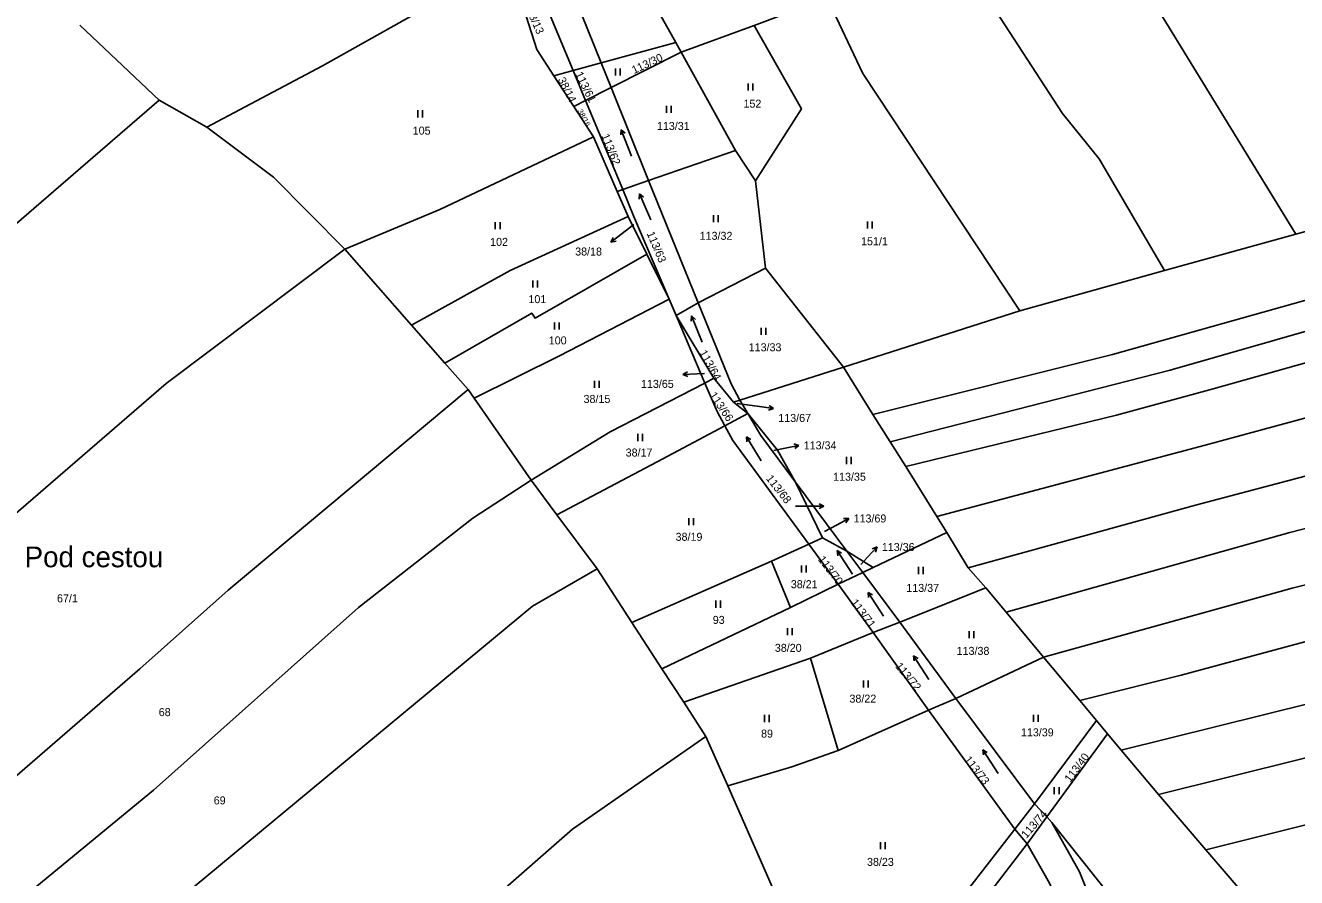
# Model space of a CAD drawing. Extents: x -7476540 to -746055, y -11317203 to -1129777.
# Drawn here: x -747546.5 to -747276.5, y -1131322.6 to -1131141.4 of the extents above; entities that cross this region are included whole.
import ezdxf

# ---------------------------------------------------------------- set-up
doc = ezdxf.new("R2010")
doc.units = 0
for name, color, linetype in [('Hranice parcel', 7, 'Continuous'), ('Parcelní čísla', 7, 'Continuous'), ('Pop  PČ popisy', 7, 'Continuous'), ('Značky kultur', 7, 'Continuous')]:
    doc.layers.add(name, color=color, linetype=linetype)

msp = doc.modelspace()

# ---------------------------------------------------------------- linework, layer by layer
at = {"layer": 'Hranice parcel'}
for p, q in [((-747408.38, -1131145.07), (-747431.95, -1131103.02)), ((-747440.84, -1131108.03), (-747424.22, -1131149.41)), ((-747430.18, -1131151.04), (-747446.81, -1131111.05)), ((-747376.22, -1131135.6), (-747391.74, -1131141.48)), ((-747518.15, -1131157.34), (-747534.94, -1131141.41)), ((-747407.22, -1131147.14), (-747391.74, -1131141.48)), ((-747424.22, -1131149.41), (-747408.38, -1131145.07)), ((-747407.22, -1131147.14), (-747408.38, -1131145.07)), ((-747422.11, -1131154.66), (-747407.22, -1131147.14)), ((-747395.7, -1131168), (-747407.22, -1131147.14)), ((-747430.18, -1131151.04), (-747424.22, -1131149.41)), ((-747424.22, -1131149.41), (-747422.11, -1131154.66)), ((-747434.26, -1131152.16), (-747430.18, -1131151.04)), ((-747434.26, -1131152.16), (-747430.03, -1131158.67)), ((-747427.53, -1131157.41), (-747430.18, -1131151.04)), ((-747427.53, -1131157.41), (-747422.11, -1131154.66)), ((-747422.11, -1131154.66), (-747414.16, -1131174.44)), ((-747508, -1131163.09), (-747518.15, -1131157.34)), ((-747430.03, -1131158.67), (-747427.53, -1131157.41)), ((-747430.03, -1131158.67), (-747425.84, -1131165.11)), ((-747419.66, -1131176.34), (-747427.53, -1131157.41)), ((-747425.84, -1131165.11), (-747420.83, -1131176.75)), ((-747414.16, -1131174.44), (-747395.7, -1131168)), ((-747391.42, -1131174.47), (-747395.7, -1131168)), ((-747419.66, -1131176.34), (-747414.16, -1131174.44)), ((-747414.16, -1131174.44), (-747403.63, -1131200.37)), ((-747389.33, -1131193.02), (-747391.42, -1131174.47)), ((-747420.83, -1131176.75), (-747419.66, -1131176.34)), ((-747420.83, -1131176.75), (-747418.53, -1131182.09)), ((-747418.53, -1131182.09), (-747414.55, -1131190.08)), ((-747304.55, -1131193.5), (-747276.68, -1131185.78)), ((-747464.5, -1131205.17), (-747478.68, -1131189)), ((-747414.55, -1131190.08), (-747409.79, -1131199.63)), ((-747403.63, -1131200.37), (-747389.33, -1131193.02)), ((-747372.79, -1131214.07), (-747389.33, -1131193.02)), ((-747335.3, -1131202.07), (-747304.55, -1131193.5)), ((-747408.32, -1131203.08), (-747409.79, -1131199.63)), ((-747408.32, -1131203.08), (-747403.63, -1131200.37)), ((-747372.79, -1131214.07), (-747335.3, -1131202.07)), ((-747402.18, -1131217.46), (-747408.32, -1131203.08)), ((-747408.32, -1131203.08), (-747400.3, -1131216.43)), ((-747457.41, -1131213.25), (-747464.5, -1131205.17)), ((-747452.5, -1131218.84), (-747457.41, -1131213.25)), ((-747394.81, -1131221.1), (-747372.79, -1131214.07)), ((-747366.49, -1131224.14), (-747372.79, -1131214.07)), ((-747402.18, -1131217.46), (-747400.3, -1131216.43)), ((-747400.3, -1131216.43), (-747396.13, -1131221.54)), ((-747451.24, -1131220.66), (-747452.5, -1131218.84)), ((-747451.24, -1131220.66), (-747439.12, -1131238.12)), ((-747396.13, -1131221.54), (-747394.81, -1131221.1)), ((-747393.08, -1131223.94), (-747396.13, -1131221.54)), ((-747394.81, -1131221.1), (-747393.08, -1131223.94)), ((-747397.95, -1131226.54), (-747393.08, -1131223.94)), ((-747362.83, -1131229.98), (-747366.49, -1131224.14)), ((-747359.55, -1131235.22), (-747362.83, -1131229.98)), ((-747352.93, -1131245.79), (-747359.55, -1131235.22)), ((-747439.12, -1131238.12), (-747433.68, -1131245.43)), ((-747377.23, -1131250.36), (-747382.92, -1131238.52)), ((-747382.92, -1131238.52), (-747372.02, -1131253.19)), ((-747433.68, -1131245.43), (-747425.11, -1131256.95)), ((-747350.79, -1131249.21), (-747352.93, -1131245.79)), ((-747380.11, -1131251.72), (-747377.23, -1131250.36)), ((-747377.23, -1131250.36), (-747372.02, -1131253.19)), ((-747366.48, -1131256.66), (-747350.79, -1131249.21)), ((-747346.25, -1131256.73), (-747350.79, -1131249.21)), ((-747388.07, -1131255.34), (-747380.11, -1131251.72)), ((-747373.91, -1131260.21), (-747380.11, -1131251.72)), ((-747372.02, -1131253.19), (-747366.48, -1131256.66)), ((-747372.02, -1131253.19), (-747368.67, -1131257.7)), ((-747417.7, -1131268.35), (-747388.07, -1131255.34)), ((-747388.07, -1131255.34), (-747384.01, -1131265.18)), ((-747425.11, -1131256.95), (-747417.7, -1131268.35)), ((-747373.91, -1131260.21), (-747368.67, -1131257.7)), ((-747368.67, -1131257.7), (-747366.48, -1131256.66)), ((-747368.67, -1131257.7), (-747360.8, -1131268.29)), ((-747342.53, -1131260.96), (-747346.25, -1131256.73)), ((-747373.91, -1131260.21), (-747384.01, -1131265.18)), ((-747366.42, -1131270.45), (-747373.91, -1131260.21)), ((-747360.8, -1131268.29), (-747342.53, -1131260.96)), ((-747338.19, -1131266.17), (-747342.53, -1131260.96)), ((-747384.01, -1131265.18), (-747411.33, -1131278.16)), ((-747330.24, -1131275.71), (-747338.19, -1131266.17)), ((-747411.33, -1131278.16), (-747417.7, -1131268.35)), ((-747366.42, -1131270.45), (-747360.8, -1131268.29)), ((-747360.8, -1131268.29), (-747348.89, -1131284.46)), ((-747379.74, -1131275.95), (-747366.42, -1131270.45)), ((-747354.67, -1131286.99), (-747366.42, -1131270.45)), ((-747406.7, -1131285.28), (-747379.74, -1131275.95)), ((-747379.74, -1131275.95), (-747373.86, -1131295.58)), ((-747348.89, -1131284.46), (-747330.24, -1131275.71)), ((-747322.57, -1131284.9), (-747330.24, -1131275.71)), ((-747411.33, -1131278.16), (-747406.7, -1131285.28)), ((-747401.97, -1131292.55), (-747406.7, -1131285.28)), ((-747354.67, -1131286.99), (-747348.89, -1131284.46)), ((-747348.89, -1131284.46), (-747332.21, -1131306.86)), ((-747319.02, -1131289.16), (-747322.57, -1131284.9)), ((-747373.86, -1131295.58), (-747354.67, -1131286.99)), ((-747336.38, -1131312.26), (-747354.67, -1131286.99)), ((-747332.21, -1131306.86), (-747319.02, -1131289.16)), ((-747316.65, -1131292.01), (-747319.02, -1131289.16)), ((-747397.34, -1131303.04), (-747401.97, -1131292.55)), ((-747316.65, -1131292.01), (-747329.56, -1131309.63)), ((-747313.75, -1131295.48), (-747316.65, -1131292.01)), ((-747305.83, -1131304.88), (-747313.75, -1131295.48)), ((-747397.34, -1131303.04), (-747384.78, -1131331.55)), ((-747336.38, -1131312.26), (-747332.21, -1131306.86)), ((-747332.21, -1131306.86), (-747329.56, -1131309.63)), ((-747295.77, -1131316.67), (-747305.83, -1131304.88)), ((-747329.56, -1131309.63), (-747333.76, -1131315.41)), ((-747328.48, -1131310.88), (-747329.56, -1131309.63)), ((-747370.27, -1131355.92), (-747336.38, -1131312.26)), ((-747333.76, -1131315.41), (-747336.38, -1131312.26)), ((-747286.32, -1131327.71), (-747295.77, -1131316.67))]:
    msp.add_line(p, q, dxfattribs=at)
for points in [[(-747455.08, -1130941.09), (-747407, -1130998.24), (-747346.3, -1131076.82), (-747308.86, -1131133.19), (-747276.68, -1131185.78)], [(-747466.65, -1130957.41), (-747426.05, -1131003.14), (-747390.52, -1131051.98), (-747379.77, -1131069.99), (-747357.62, -1131107.84), (-747342.16, -1131135.57), (-747326.23, -1131160.19), (-747318.42, -1131169.83), (-747304.55, -1131193.5)], [(-747444.14, -1131128.36), (-747441.29, -1131135.89), (-747437.88, -1131146.58), (-747434.26, -1131152.16)], [(-747376.22, -1131135.6), (-747368.67, -1131151.69), (-747335.3, -1131202.07)], [(-747464.26, -1131139.24), (-747483.41, -1131150.03), (-747508, -1131163.09)], [(-747366.49, -1131224.14), (-747315.64, -1131211.37), (-747239.01, -1131189.85), (-747208.02, -1131183.24), (-747142.94, -1131169.86), (-747059.23, -1131151.85), (-746994.26, -1131139.92)], [(-747391.74, -1131141.48), (-747381.7, -1131159.18), (-747391.42, -1131174.47)], [(-747362.83, -1131229.98), (-747303.37, -1131214.71), (-747236.14, -1131195.43), (-747183.65, -1131184.91), (-747140.79, -1131175.19), (-747094.5, -1131166.43), (-747035.79, -1131154.71), (-746990.07, -1131145.5)], [(-747359.55, -1131235.22), (-747314.76, -1131224.28), (-747294.21, -1131218.7), (-747239.88, -1131203.41), (-747217.65, -1131198.22), (-747179.1, -1131189.54), (-747110.35, -1131174.95), (-747094.58, -1131172.24), (-747057.06, -1131164.91), (-746987.65, -1131152.16)], [(-747637.6, -1131258.56), (-747605.36, -1131233.4), (-747586.04, -1131216.89), (-747564.17, -1131197.09), (-747518.15, -1131157.34)], [(-747478.68, -1131189), (-747493.84, -1131173.69), (-747508, -1131163.09)], [(-747352.93, -1131245.79), (-747295.96, -1131230.66), (-747233.75, -1131213.76), (-747157.12, -1131196.99), (-747060.9, -1131176.27), (-747030, -1131171.43), (-746983.59, -1131163.34)], [(-747425.84, -1131165.11), (-747458.47, -1131180.59), (-747478.68, -1131189)], [(-747409.79, -1131199.63), (-747417.35, -1131181.9), (-747419.66, -1131176.34)], [(-747346.25, -1131256.73), (-747297.98, -1131243.4), (-747234.57, -1131226.59), (-747209.63, -1131221.41), (-747174.99, -1131213.76), (-747135.39, -1131204.28), (-747094.05, -1131195.6), (-747052.94, -1131188.25), (-746980.29, -1131175.39)], [(-747276.68, -1131185.78), (-747264.57, -1131182.48), (-747243.06, -1131175.98)], [(-747418.53, -1131182.09), (-747443.59, -1131193.55), (-747464.5, -1131205.17)], [(-747338.19, -1131266.17), (-747277.98, -1131249.2), (-747235.43, -1131238.28), (-747213.21, -1131234.14), (-747187.16, -1131228.96), (-747140.48, -1131218.28), (-747086.15, -1131207.37), (-747047.59, -1131199.64), (-746976.21, -1131185.45)], [(-747478.68, -1131189), (-747516.61, -1131217.55), (-747562.75, -1131257.36), (-747584.62, -1131275.69), (-747613.72, -1131296.16)], [(-747414.55, -1131190.08), (-747438.27, -1131203.66), (-747438.96, -1131202.58), (-747457.41, -1131213.25)], [(-747330.24, -1131275.71), (-747277.42, -1131261.08), (-747228.35, -1131248.89), (-747189.96, -1131241.4), (-747149.33, -1131232.63), (-747125.6, -1131227.7), (-747062.34, -1131215.02), (-746993.98, -1131202.44), (-746969.25, -1131197.46)], [(-747409.79, -1131199.63), (-747433.07, -1131211.69), (-747451.24, -1131220.66)], [(-747403.63, -1131200.37), (-747396.62, -1131217.65), (-747394.81, -1131221.1)], [(-747322.57, -1131284.9), (-747301.01, -1131279.52), (-747228.28, -1131259.93), (-747190.83, -1131253.47), (-747160.64, -1131247.09), (-747111.02, -1131236.65), (-747064.81, -1131227), (-747042.19, -1131222.79), (-746964.73, -1131206.9)], [(-747439.12, -1131238.12), (-747422.3, -1131227.8), (-747402.18, -1131217.46)], [(-747397.95, -1131226.54), (-747399.59, -1131223.53), (-747402.18, -1131217.46)], [(-747587.97, -1131330.74), (-747567.99, -1131317.8), (-747522.26, -1131278.21), (-747503.48, -1131261.46), (-747452.5, -1131218.84)], [(-747313.75, -1131295.48), (-747253.05, -1131280.4), (-747231.07, -1131274.58), (-747201.09, -1131268.16), (-747174.02, -1131263.18), (-747155.54, -1131259.35), (-747082.77, -1131244.23), (-747040.5, -1131235.77), (-746958.82, -1131219.23)], [(-747393.08, -1131223.94), (-747390.29, -1131228.61), (-747382.92, -1131238.52)], [(-747382.92, -1131238.52), (-747386.77, -1131231.73), (-747393.08, -1131223.94)], [(-747433.68, -1131245.43), (-747412.33, -1131234.19), (-747397.95, -1131226.54)], [(-747380.11, -1131251.72), (-747396.26, -1131229.64), (-747397.95, -1131226.54)], [(-747305.83, -1131304.88), (-747229.31, -1131285.82), (-747172.59, -1131275.8), (-747161.6, -1131273.01), (-747136.9, -1131266.58), (-747124.63, -1131263.55), (-747104.54, -1131259.94), (-747060.99, -1131251.11), (-747007.85, -1131241), (-746953.9, -1131229.5)], [(-747573.75, -1131348.78), (-747519.29, -1131304), (-747475.75, -1131265.13), (-747451.48, -1131246.17), (-747439.12, -1131238.12)], [(-747295.77, -1131316.67), (-747260.4, -1131307.82), (-747220.48, -1131297.78), (-747153.89, -1131284.38), (-747109.03, -1131274.27), (-747084.89, -1131269.09), (-747048.4, -1131261.6), (-746996.46, -1131251.25), (-746948.48, -1131240.82)], [(-747560.74, -1131366.12), (-747532.83, -1131342.86), (-747438.82, -1131264.87), (-747425.11, -1131256.95)], [(-747534.26, -1131400.17), (-747480.38, -1131356.14), (-747430.3, -1131312.29), (-747401.97, -1131292.55)], [(-747373.86, -1131295.58), (-747383.75, -1131299), (-747397.34, -1131303.04)], [(-747281.5, -1131480.62), (-747293.52, -1131448.9), (-747294.79, -1131442.89), (-747294.49, -1131425.32), (-747301.04, -1131375.44), (-747322.63, -1131321.35), (-747328.48, -1131310.88)], [(-747281.5, -1131480.62), (-747268.38, -1131439.1), (-747266.03, -1131410.81), (-747274.76, -1131385.48), (-747283.22, -1131370.63), (-747296.93, -1131350.55), (-747328.48, -1131310.88)], [(-747333.76, -1131315.41), (-747364.89, -1131355.97), (-747369.3, -1131361.68), (-747376.46, -1131367.68)], [(-747333.76, -1131315.41), (-747328.97, -1131323.74), (-747306.78, -1131376.04), (-747305.04, -1131391.08)]]:
    msp.add_lwpolyline(points, dxfattribs=at)
at = {"layer": 'Pop  PČ popisy'}
for p, q in [((-747419.78, -1131185.67), (-747422.15, -1131187.52)), ((-747417.31, -1131183.76), (-747419.78, -1131185.67)), ((-747422.15, -1131187.52), (-747421.66, -1131186.51)), ((-747422.15, -1131187.52), (-747421.05, -1131187.3)), ((-747406.87, -1131215.61), (-747405.89, -1131215.08)), ((-747403.87, -1131215.51), (-747406.87, -1131215.61)), ((-747406.87, -1131215.61), (-747405.85, -1131216.08)), ((-747402.28, -1131215.44), (-747403.87, -1131215.51)), ((-747395.32, -1131221.83), (-747390.57, -1131222.47)), ((-747390.57, -1131222.47), (-747387.6, -1131222.89)), ((-747387.6, -1131222.89), (-747388.66, -1131223.24)), ((-747387.6, -1131222.89), (-747388.52, -1131222.25)), ((-747387.54, -1131231.81), (-747385.15, -1131231.31)), ((-747385.15, -1131231.31), (-747382.21, -1131230.69)), ((-747382.21, -1131230.69), (-747383.3, -1131230.4)), ((-747382.21, -1131230.69), (-747383.09, -1131231.38)), ((-747376.82, -1131248.99), (-747374.26, -1131247.63)), ((-747374.26, -1131247.63), (-747371.61, -1131246.22)), ((-747371.61, -1131246.22), (-747372.73, -1131246.25)), ((-747371.61, -1131246.22), (-747372.26, -1131247.13)), ((-747367.66, -1131254.49), (-747365.61, -1131252.29)), ((-747365.61, -1131252.29), (-747366.66, -1131252.69)), ((-747365.61, -1131252.29), (-747365.93, -1131253.37)), ((-747369.1, -1131256.04), (-747367.66, -1131254.49))]:
    msp.add_line(p, q, dxfattribs=at)
at = {"layer": 'Značky kultur'}
for p, q in [((-747421.19, -1131152.09), (-747421.19, -1131150.59)), ((-747420.19, -1131152.09), (-747420.19, -1131150.59)), ((-747393.01, -1131155.26), (-747393.01, -1131153.76)), ((-747392.01, -1131155.26), (-747392.01, -1131153.76)), ((-747410.37, -1131160.06), (-747410.37, -1131158.56)), ((-747409.37, -1131160.06), (-747409.37, -1131158.56)), ((-747463.19, -1131160.99), (-747463.19, -1131159.49)), ((-747462.19, -1131160.99), (-747462.19, -1131159.49)), ((-747419.95, -1131163.62), (-747420.07, -1131164.71)), ((-747417.8, -1131169.22), (-747419.95, -1131163.62)), ((-747419.95, -1131163.62), (-747419.14, -1131164.35)), ((-747416.12, -1131177.27), (-747416.18, -1131178.37)), ((-747413.68, -1131182.75), (-747416.12, -1131177.27)), ((-747416.12, -1131177.27), (-747415.26, -1131177.96)), ((-747400.35, -1131183.28), (-747400.35, -1131181.78)), ((-747399.35, -1131183.28), (-747399.35, -1131181.78)), ((-747367.65, -1131184.63), (-747367.65, -1131183.13)), ((-747366.65, -1131184.63), (-747366.65, -1131183.13)), ((-747446.72, -1131184.75), (-747446.72, -1131183.25)), ((-747445.72, -1131184.75), (-747445.72, -1131183.25)), ((-747438.74, -1131197.17), (-747438.74, -1131195.67)), ((-747437.74, -1131197.17), (-747437.74, -1131195.67)), ((-747434.17, -1131206.06), (-747434.17, -1131204.56)), ((-747433.17, -1131206.06), (-747433.17, -1131204.56)), ((-747405.02, -1131203.2), (-747405.12, -1131204.29)), ((-747402.78, -1131208.76), (-747405.02, -1131203.2)), ((-747405.02, -1131203.2), (-747404.19, -1131203.92)), ((-747390.28, -1131207.21), (-747390.28, -1131205.71)), ((-747389.28, -1131207.21), (-747389.28, -1131205.71)), ((-747425.63, -1131218.5), (-747425.63, -1131217)), ((-747424.63, -1131218.5), (-747424.63, -1131217)), ((-747416.42, -1131229.77), (-747416.42, -1131228.27)), ((-747415.42, -1131229.77), (-747415.42, -1131228.27)), ((-747390.27, -1131234), (-747393.36, -1131228.86)), ((-747393.36, -1131228.86), (-747393.28, -1131229.96)), ((-747393.36, -1131228.86), (-747392.42, -1131229.44)), ((-747372.15, -1131234.66), (-747372.15, -1131233.16)), ((-747371.15, -1131234.66), (-747371.15, -1131233.16)), ((-747382.94, -1131243.61), (-747376.94, -1131243.61)), ((-747376.94, -1131243.61), (-747377.92, -1131243.11)), ((-747376.94, -1131243.61), (-747377.92, -1131244.11)), ((-747405.62, -1131247.67), (-747405.62, -1131246.17)), ((-747404.62, -1131247.67), (-747404.62, -1131246.17)), ((-747370.84, -1131258.1), (-747374.11, -1131253.06)), ((-747374.11, -1131253.06), (-747373.99, -1131254.16)), ((-747374.11, -1131253.06), (-747373.15, -1131253.61)), ((-747381.66, -1131257.75), (-747381.66, -1131256.25)), ((-747380.66, -1131257.75), (-747380.66, -1131256.25)), ((-747356.81, -1131258.04), (-747356.81, -1131256.54)), ((-747355.81, -1131258.04), (-747355.81, -1131256.54)), ((-747399.86, -1131265.2), (-747399.86, -1131263.7)), ((-747398.86, -1131265.2), (-747398.86, -1131263.7)), ((-747364.28, -1131266.98), (-747367.55, -1131261.95)), ((-747367.55, -1131261.95), (-747367.43, -1131263.04)), ((-747367.55, -1131261.95), (-747366.59, -1131262.49)), ((-747384.65, -1131271.02), (-747384.65, -1131269.52)), ((-747383.65, -1131271.02), (-747383.65, -1131269.52)), ((-747346.06, -1131271.67), (-747346.06, -1131270.17)), ((-747345.06, -1131271.67), (-747345.06, -1131270.17)), ((-747354.6, -1131280.46), (-747357.87, -1131275.43)), ((-747357.87, -1131275.43), (-747357.75, -1131276.52)), ((-747357.87, -1131275.43), (-747356.91, -1131275.97)), ((-747368.52, -1131282.18), (-747368.52, -1131280.68)), ((-747367.52, -1131282.18), (-747367.52, -1131280.68)), ((-747389.55, -1131289.49), (-747389.55, -1131287.99)), ((-747388.55, -1131289.49), (-747388.55, -1131287.99)), ((-747332.42, -1131289.43), (-747332.42, -1131287.93)), ((-747331.42, -1131289.43), (-747331.42, -1131287.93)), ((-747339.9, -1131300.44), (-747343.17, -1131295.41)), ((-747343.17, -1131295.41), (-747343.05, -1131296.5)), ((-747343.17, -1131295.41), (-747342.21, -1131295.95)), ((-747327.98, -1131304.85), (-747327.98, -1131303.35)), ((-747326.98, -1131304.85), (-747326.98, -1131303.35)), ((-747364.9, -1131316.52), (-747364.9, -1131315.02)), ((-747363.9, -1131316.52), (-747363.9, -1131315.02))]:
    msp.add_line(p, q, dxfattribs=at)

# ---------------------------------------------------------------- texts
at = {"layer": 'Parcelní čísla'}
for s, height, rotation, p in [('38/13', 1.7, 294, (-747440.15, -1131138.28)), ('113/30', 1.7, 25, (-747417.25, -1131151.8)), ('38/14', 1.7, 297, (-747433.5, -1131152.97)), ('113/61', 1.7, 296, (-747429.79, -1131151.77)), ('38/16', 1.14, 298, (-747429.27, -1131159.6)), ('113/62', 1.7, 292, (-747424.23, -1131164.87)), ('113/63', 1.7, 293, (-747414.6, -1131185.65)), ('113/64', 1.7, 299, (-747403.45, -1131210.99)), ('113/66', 1.7, 304, (-747401.33, -1131220.04)), ('113/68', 1.7, 308, (-747389.31, -1131237.77)), ('113/70', 1.7, 307, (-747378.26, -1131254.96)), ('113/71', 1.7, 307, (-747371.32, -1131264.14)), ('113/72', 1.7, 310, (-747361.86, -1131277.71)), ('113/40', 1.7, 53, (-747324.61, -1131302.46)), ('113/73', 1.7, 308, (-747347.22, -1131297.52)), ('113/74', 1.7, 49, (-747333.89, -1131314.34))]:
    msp.add_text(s, height=height, rotation=rotation, dxfattribs=at).set_placement(p)
for s, p in [('152', (-747394, -1131158.92)), ('105', (-747464.26, -1131164.66)), ('113/31', (-747412.39, -1131163.67)), ('113/32', (-747403.31, -1131187.01)), ('102', (-747447.82, -1131188.3)), ('38/18', (-747429.75, -1131190.35)), ('151/1', (-747369.02, -1131188.17)), ('101', (-747439.68, -1131200.47)), ('100', (-747435.36, -1131209.24)), ('113/33', (-747392.89, -1131210.7)), ('113/65', (-747415.77, -1131218.48)), ('38/15', (-747427.97, -1131221.68)), ('113/67', (-747386.6, -1131225.72)), ('38/17', (-747419.03, -1131233.07)), ('113/34', (-747381.21, -1131231.55)), ('113/35', (-747374.96, -1131238.21)), ('113/69', (-747370.61, -1131247.08)), ('38/19', (-747408.42, -1131250.98)), ('113/36', (-747364.61, -1131253.15)), ('38/21', (-747383.95, -1131261.05)), ('113/37', (-747359.41, -1131261.84)), ('67/1', (-747539.82, -1131264.06)), ('93', (-747400.52, -1131268.64)), ('38/20', (-747387.34, -1131274.58)), ('113/38', (-747348.72, -1131275.22)), ('38/22', (-747371.49, -1131285.37)), ('68', (-747518.21, -1131288.24)), ('89', (-747390.27, -1131292.8)), ('113/39', (-747335.06, -1131292.54)), ('69', (-747506.53, -1131307)), ('38/23', (-747367.76, -1131320.07))]:
    msp.add_text(s, height=1.7, dxfattribs=at).set_placement(p)
at = {"layer": 'Pop  PČ popisy'}
msp.add_text('Pod cestou', height=4.4, dxfattribs=at).set_placement((-747546.7, -1131256.6))

doc.saveas('drawing.dxf')
